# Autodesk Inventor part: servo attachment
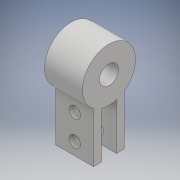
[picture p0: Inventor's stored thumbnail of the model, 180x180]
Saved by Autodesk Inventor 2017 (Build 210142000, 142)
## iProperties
Created: 2017-04
Part Number: servo attachment
Material: Generic
Document SubType Name: Modeling
Designer: s4321966
Density: 1 g/cm^3
Appearance: Default
Author: s4321966
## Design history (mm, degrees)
sketch "Sketch1" dims "d0" = 7
  geometry: L1 (0, -3.5)-(1, -3.5); L2 (1, -3.5)-(1, -9.5); L3 (1, -9.5)-(0, -9.5); L4 (0, -9.5)-(0, -3.5); L5 (1, -9.5)-(2.028, -9.5); L6 (2.028, -9.5)-(2.028, -1.25); L7 (2.028, -1.25)-(1, -1.25); L8 (1, -1.25)-(1, -9.5); L9 (0, -3.5)-(-1, -3.5); L10 (-1, -3.5)-(-1, -9.5); L11 (-1, -9.5)-(0, -9.5); L12 (-1, -9.5)-(-2.028, -9.5); L13 (-2.028, -9.5)-(-2.028, -1.25); L14 (-2.028, -1.25)-(-1, -1.25); L15 (-1, -1.25)-(-1, -9.5); C1 r 1.25 at (0, 0); 2 further points
  constraints: 30 end point, 5 symmetric about line, 4 coincident, 4 parallel, 2 horizontal, 2 perpendicular, 1 centre point, 1 vertical alignment, 2 other
  dimensions: "d1" = 2.5 diameter of C1; "d2" = 1 distance of L2.end L3.end; "d3" = 6 distance of L1.end L2.end
extrude "Extrusion1" new body sketch "Sketch1" distance "d4" = 5; taper "d5" = 0 deg
sketch "Sketch2"
  geometry: L1 (0, 6.647)-(5, 6.647) reference; L2 (2.5, 6.647)-(2.5, 0); L3 (5, 0)-(0, 0) reference; L4 (2.5, 3.324)-(0, 6.647); L5 (0, 6.647)-(5.07, 3.324); L6 (5.07, 3.324)-(0, 0); C1 r 0.75 at (2.535, 1.662); C2 r 0.75 at (2.535, 4.985); 1 further point
  constraints: 8 end point, 5 midpoint, 2 centre point
  dimensions: "d6" = 1.5 diameter of C1; "d7" = 1.5 diameter of C2
extrude "Extrusion2" cut sketch "Sketch2" distance "d8" = 5; taper "d9" = 0 deg
body "Solid1"
